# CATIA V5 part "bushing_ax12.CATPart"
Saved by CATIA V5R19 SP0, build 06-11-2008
Part number: bushing_ax12
Bounding box of the stored display mesh (mm): x -5.5 to 5.5, y -5.5 to 5.5, z 3.653 to 10.753
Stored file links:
  C:\Users\Rémi\Documents\BTS CPI\Projet 04- Guitar Elec\Maquette 3D\Moteur\bushing_ax12.CATPart
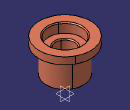
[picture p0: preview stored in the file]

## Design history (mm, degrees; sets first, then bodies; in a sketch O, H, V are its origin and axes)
Body1 (main body)
  Sketch1 on yz-plane, origin (0, 0, 0), H (0, 1, 0), V (0, 0, 1)
    line L1 (2, 3.6529) -> (2, 8.7529)
    line L2 (3.5, 10.7529) -> (5.5, 10.7529)
    line L3 (5.5, 10.7529) -> (5.5, 9.2529)
    line L4 (5.5, 9.2529) -> (4, 9.2529)
    line L5 (4, 9.2529) -> (4, 3.6529)
    line L6 (4, 3.6529) -> (2, 3.6529)
    line L7 (2, 8.7529) -> (3.5, 8.7529)
    line L8 (3.5, 8.7529) -> (3.5, 10.7529)
    axis line L9 (0, 19.4736) -> (0, -7.1048)
    point P9 (0, 19.4736)
    distance L1 V = 2
    length L5 = 5.6
    distance V L5 = 4
    distance L3 V = 5.5
    length L3 = 1.5
    distance L7 L2 = 2
    distance L8 V = 3.5
    vertical: L1 V, L3 V, L5 V, L8 V, L9 V
    horizontal: L2 H, L4 H, L6 H, L7 H
    coincidence: P9 V
  Shaft1: profile Sketch1, axis Sketch1.L9, angle 360
  Chamfer1: length 0.2, angle 45, on edge [face of Shaft1 from Sketch1.L1 | face of Shaft1 from Sketch1.L7]; edge [face of Shaft1 from Sketch1.L8 | face of Shaft1 from Sketch1.L2]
